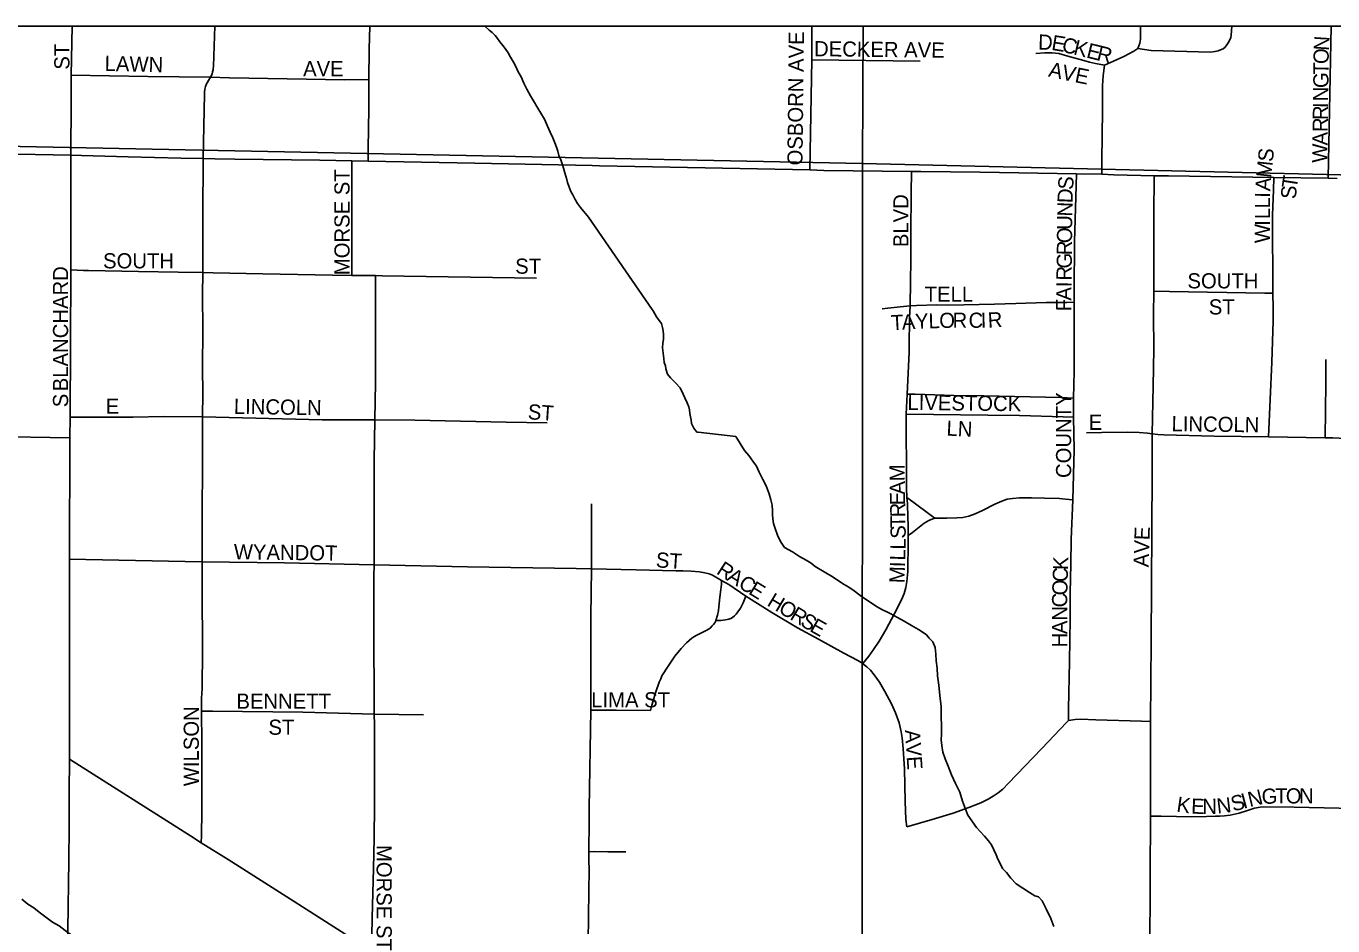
# Model space of a CAD drawing. Extents: x 0 to 68, y 0 to 52.9.
# Drawn here: x 43.794 to 44.871, y 41.267 to 42.008 of the extents above; entities that cross this region are included whole.
import ezdxf

# ---------------------------------------------------------------- set-up
doc = ezdxf.new("R2010")
doc.units = 0
for name, color, linetype in [('Default', 7, 'Continuous'), ('GM_X_Minor_River', 7, 'Continuous'), ('GM_X_State_Route', 7, 'Continuous')]:
    doc.layers.add(name, color=color, linetype=linetype)

msp = doc.modelspace()

# ---------------------------------------------------------------- linework, layer by layer
at = {"layer": 'Default'}
msp.add_line((41.1051, 42.0083), (50.3451, 42.0083), dxfattribs=at)
for points in [[(43.8309, 41.9678), (43.8317, 42.0083)], [(43.9457, 41.9661), (43.947, 41.9688), (43.9475, 41.9706), (43.9479, 41.9723), (43.948, 41.9731), (43.9483, 41.9752), (43.9492, 42.0083)], [(44.0763, 41.9642), (44.0767, 41.9894), (44.077, 42.0083)], [(44.4416, 41.9806), (44.4416, 41.9888), (44.4416, 42.0083)], [(45.8294, 42.0083), (45.8284, 41.8633), (44.4833, 41.8951), (44.484, 42.0083)], [(44.7106, 41.9899), (44.7121, 41.9942), (44.7127, 41.9977), (44.7128, 42.0016), (44.7128, 42.0083)], [(44.7106, 41.9899), (44.7215, 41.9882), (44.7704, 41.9869), (44.774, 41.9873), (44.7766, 41.9879), (44.7787, 41.9887), (44.7808, 41.9897), (44.7825, 41.9911), (44.7839, 41.9929), (44.785, 41.9945), (44.7863, 41.9969), (44.7871, 41.999), (44.7874, 42.0009), (44.7879, 42.0083)], [(44.8675, 41.8829), (44.87, 42.0083)], [(44.6264, 41.9857), (44.6339, 41.9862), (44.6398, 41.9863), (44.6452, 41.9857), (44.6528, 41.9836), (44.6589, 41.982), (44.6639, 41.9804), (44.6705, 41.9786), (44.6757, 41.9774), (44.683, 41.9761)], [(44.683, 41.9761), (44.6905, 41.9795), (44.699, 41.9833), (44.7071, 41.9877), (44.7106, 41.9899)], [(44.44, 41.8898), (44.4416, 41.9806)], [(44.4416, 41.9806), (44.531, 41.9795)], [(44.6808, 41.8863), (44.6809, 41.8976), (44.6812, 41.9387), (44.6814, 41.9592), (44.6815, 41.9634), (44.682, 41.9672), (44.6825, 41.9716), (44.683, 41.9761)], [(43.8305, 41.9018), (43.8307, 41.9461), (43.8309, 41.9678)], [(43.8309, 41.9678), (43.894, 41.9668), (43.9457, 41.9661)], [(43.9396, 41.8991), (43.9407, 41.9526), (43.9407, 41.9539), (43.9411, 41.9564), (43.9417, 41.9585), (43.9425, 41.9608), (43.943, 41.9617), (43.944, 41.9635), (43.9457, 41.9661)], [(43.9457, 41.9661), (43.9614, 41.9658), (44.0564, 41.964), (44.0763, 41.9642)], [(44.0757, 41.8969), (44.0758, 41.9073), (44.0764, 41.9402), (44.0763, 41.9642)], [(43.8304, 41.8074), (43.8305, 41.9018)], [(43.9393, 41.8051), (43.9393, 41.8523), (43.9396, 41.8991)], [(44.0622, 41.8027), (44.0623, 41.8124), (44.0624, 41.8368), (44.0623, 41.8524), (44.0623, 41.881), (44.0623, 41.8928), (44.0623, 41.8972)], [(44.5226, 41.7778), (44.5226, 41.7804), (44.523, 41.7951), (44.5233, 41.8181), (44.5233, 41.846), (44.5236, 41.8624), (44.5235, 41.8707), (44.5238, 41.8885)], [(44.658, 41.7807), (44.658, 41.7898), (44.6583, 41.8307), (44.6593, 41.8673), (44.6599, 41.8866)], [(44.7237, 41.8198), (44.7237, 41.8594), (44.7239, 41.8781), (44.724, 41.885)], [(44.8219, 41.7881), (44.8216, 41.8526), (44.8223, 41.873), (44.8226, 41.8835)], [(44.7238, 41.7898), (44.7237, 41.8034), (44.7237, 41.8198)], [(43.83, 41.686), (43.8302, 41.7461), (43.8304, 41.8074)], [(43.8304, 41.8074), (43.8411, 41.8069), (43.8452, 41.8068), (43.8862, 41.8059), (43.9191, 41.8056), (43.9393, 41.8051)], [(43.9392, 41.6863), (43.9393, 41.7058), (43.9391, 41.7263), (43.9394, 41.7581), (43.9392, 41.7868), (43.9393, 41.8051)], [(43.9393, 41.8051), (43.9478, 41.8049), (43.9889, 41.8041), (44.0463, 41.8029), (44.0622, 41.8027)], [(44.0622, 41.8027), (44.0819, 41.8026)], [(44.0813, 41.6837), (44.0819, 41.7142), (44.0819, 41.7931), (44.0819, 41.8026)], [(44.0819, 41.8026), (44.0874, 41.8025), (44.2145, 41.8004)], [(44.5226, 41.7778), (44.528, 41.7781), (44.5448, 41.7785), (44.5543, 41.7784), (44.5922, 41.7792), (44.61, 41.7797), (44.6348, 41.7804), (44.6519, 41.7806), (44.658, 41.7807)], [(44.6574, 41.7015), (44.658, 41.7235), (44.6581, 41.7604), (44.658, 41.7807)], [(44.7224, 41.6722), (44.723, 41.7114), (44.7236, 41.7421), (44.7234, 41.7707), (44.7238, 41.7898)], [(44.7238, 41.7898), (44.7366, 41.7896), (44.8153, 41.7882), (44.8219, 41.7881)], [(44.8183, 41.6698), (44.8211, 41.7314), (44.822, 41.7653), (44.822, 41.7757), (44.8219, 41.7881)], [(44.4995, 41.7752), (44.5043, 41.7757), (44.5145, 41.7768), (44.5226, 41.7778)], [(44.5203, 41.705), (44.5218, 41.7396), (44.522, 41.7494), (44.5222, 41.7625), (44.5223, 41.7681), (44.5226, 41.7778)], [(44.865, 41.6689), (44.8656, 41.7139), (44.8656, 41.7334)], [(44.5195, 41.6885), (44.5203, 41.705)], [(44.5203, 41.705), (44.5269, 41.7048), (44.5588, 41.7038), (44.5834, 41.7036), (44.6471, 41.7022), (44.6574, 41.7015)], [(44.6574, 41.686), (44.6574, 41.7015)], [(43.8297, 41.669), (43.83, 41.686)], [(43.83, 41.686), (43.8412, 41.686), (43.8819, 41.686), (43.907, 41.6866), (43.9392, 41.6863)], [(43.9389, 41.5666), (43.9392, 41.6863)], [(43.9392, 41.6863), (44.0379, 41.6838), (44.0813, 41.6837)], [(44.0806, 41.5643), (44.0806, 41.6502), (44.0813, 41.6837)], [(44.0813, 41.6837), (44.1142, 41.6836), (44.1896, 41.6817), (44.2233, 41.6812)], [(44.5195, 41.6885), (44.5869, 41.6876), (44.613, 41.6872), (44.649, 41.6863), (44.6574, 41.686)], [(44.5201, 41.6197), (44.5197, 41.6278), (44.5196, 41.6302), (44.5195, 41.6885)], [(44.6569, 41.6177), (44.6579, 41.6594), (44.6574, 41.686)], [(44.6682, 41.6729), (44.6807, 41.6734), (44.7021, 41.6735), (44.7117, 41.6733), (44.7184, 41.6727), (44.7224, 41.6722)], [(44.721, 41.4351), (44.7215, 41.5009), (44.7223, 41.6399), (44.7224, 41.6722)], [(44.7224, 41.6722), (44.7269, 41.6716), (44.7318, 41.6713), (44.7733, 41.6704), (44.8183, 41.6698)], [(44.8183, 41.6698), (44.865, 41.6689)], [(44.865, 41.6689), (44.8713, 41.6688), (44.8766, 41.6687), (44.8817, 41.6684), (44.8859, 41.6678), (44.8924, 41.6668), (44.9117, 41.6631), (44.9159, 41.6624), (44.9205, 41.6618), (44.9244, 41.6613), (44.9279, 41.6612), (44.9401, 41.6611), (44.95, 41.661)], [(44.5212, 41.5884), (44.5212, 41.5958), (44.5205, 41.6131), (44.5204, 41.6147), (44.5201, 41.6197)], [(44.5201, 41.6197), (44.525, 41.6161), (44.5401, 41.6048), (44.5431, 41.6026)], [(44.5431, 41.6026), (44.5529, 41.6028), (44.5613, 41.6029), (44.5662, 41.6033), (44.571, 41.6043), (44.5764, 41.6062), (44.5823, 41.6091), (44.5925, 41.6142), (44.5983, 41.6168), (44.6028, 41.6183), (44.6071, 41.6189), (44.613, 41.6194), (44.6229, 41.6194), (44.6336, 41.6192), (44.6459, 41.6188), (44.6508, 41.6183), (44.6569, 41.6177)], [(44.2598, 41.5609), (44.2598, 41.6144)], [(44.6533, 41.4358), (44.6532, 41.4454), (44.6542, 41.4844), (44.6546, 41.5196), (44.6548, 41.541), (44.6553, 41.5648), (44.6555, 41.5853), (44.6569, 41.6177)], [(44.5212, 41.5884), (44.5246, 41.591), (44.5344, 41.5986), (44.5381, 41.6008), (44.5401, 41.6016), (44.5431, 41.6026)], [(44.4837, 41.4828), (44.4885, 41.489), (44.4926, 41.4943), (44.4971, 41.5012), (44.5026, 41.5105), (44.5099, 41.5242), (44.5156, 41.5353), (44.5178, 41.5407), (44.5192, 41.5455), (44.52, 41.5505), (44.5207, 41.5588), (44.5212, 41.5834), (44.5212, 41.5884)], [(43.8295, 41.5688), (43.8428, 41.5686), (43.9247, 41.5671), (43.9389, 41.5666)], [(43.9384, 41.4437), (43.9384, 41.4542), (43.9388, 41.462), (43.9391, 41.4942), (43.9388, 41.5434), (43.9389, 41.5666)], [(43.9389, 41.5666), (44.0067, 41.5658), (44.0806, 41.5643)], [(44.0807, 41.4412), (44.0808, 41.4519), (44.0803, 41.507), (44.0805, 41.5548), (44.0806, 41.5643)], [(44.0806, 41.5643), (44.1576, 41.5626), (44.2474, 41.5612), (44.2598, 41.5609)], [(44.2593, 41.4444), (44.2595, 41.5216), (44.2598, 41.5609)], [(44.2598, 41.5609), (44.2967, 41.56), (44.3294, 41.5593), (44.3353, 41.5592), (44.3421, 41.559), (44.3491, 41.5584), (44.3533, 41.5577), (44.3569, 41.5569), (44.3597, 41.5558)], [(44.3672, 41.5514), (44.3597, 41.5558)], [(44.3625, 41.5183), (44.3638, 41.5226), (44.3646, 41.5267), (44.3655, 41.5351), (44.3662, 41.5419), (44.367, 41.5479), (44.3672, 41.5514)], [(44.3873, 41.5385), (44.3731, 41.5479), (44.3672, 41.5514)], [(44.3625, 41.5183), (44.3666, 41.5184), (44.3704, 41.5189), (44.3732, 41.5195), (44.3748, 41.5201), (44.3761, 41.5209), (44.3778, 41.5222), (44.3792, 41.5235), (44.3807, 41.5254), (44.3827, 41.5285), (44.385, 41.533), (44.3873, 41.5385)], [(44.4837, 41.4828), (44.4796, 41.4854), (44.4679, 41.4914), (44.447, 41.5028), (44.4297, 41.5122), (44.4086, 41.5248), (44.3873, 41.5385)], [(44.3086, 41.4442), (44.3096, 41.4484), (44.313, 41.4595), (44.3158, 41.4675), (44.317, 41.4702), (44.318, 41.4727), (44.3231, 41.4808), (44.3286, 41.4889), (44.3338, 41.4953), (44.3383, 41.5), (44.3427, 41.5037), (44.3444, 41.5048), (44.3469, 41.5062), (44.355, 41.5103), (44.3577, 41.5121), (44.3595, 41.5138), (44.3605, 41.5151), (44.3615, 41.5164), (44.3624, 41.5181), (44.3625, 41.5183)], [(44.5199, 41.3481), (44.5192, 41.3543), (44.5187, 41.369), (44.518, 41.3961), (44.517, 41.4125), (44.5162, 41.4217), (44.5154, 41.4266), (44.5136, 41.4339), (44.5106, 41.4421), (44.5074, 41.4496), (44.5019, 41.4597), (44.4973, 41.4675), (44.4931, 41.4736), (44.4899, 41.4774), (44.487, 41.4802), (44.4838, 41.4827), (44.4837, 41.4828)], [(43.9381, 41.335), (43.9382, 41.341), (43.9386, 41.3611), (43.9385, 41.3929), (43.9386, 41.4173), (43.9384, 41.4437)], [(43.9384, 41.4437), (43.9474, 41.4436), (44.0218, 41.4428), (44.0807, 41.4412)], [(44.076, 41.2479), (44.0773, 41.2513), (44.0787, 41.256), (44.0788, 41.2582), (44.0791, 41.2732), (44.0801, 41.314), (44.0806, 41.3389), (44.0809, 41.366), (44.081, 41.4325), (44.0807, 41.4412)], [(44.0807, 41.4412), (44.1213, 41.4405)], [(44.2577, 41.3276), (44.258, 41.3529), (44.2581, 41.3635), (44.2593, 41.4444)], [(44.2593, 41.4444), (44.2676, 41.4444), (44.2803, 41.4444), (44.3086, 41.4442)], [(44.5199, 41.3481), (44.5408, 41.3542), (44.5581, 41.3595), (44.5712, 41.3641), (44.5811, 41.3681), (44.5871, 41.3709), (44.5913, 41.3734), (44.5954, 41.3762), (44.5991, 41.3794), (44.6037, 41.3841), (44.6242, 41.4054), (44.6312, 41.4129), (44.6517, 41.4343), (44.6533, 41.4358)], [(44.6533, 41.4358), (44.6587, 41.4367), (44.6636, 41.4371), (44.6759, 41.4365), (44.7134, 41.4353), (44.721, 41.4351)], [(44.7209, 41.357), (44.7208, 41.4151), (44.721, 41.4351)], [(43.8266, 41.066), (43.8267, 41.0706), (43.8269, 41.1158), (43.8274, 41.1526), (43.8276, 41.2059), (43.8281, 41.2634), (43.8288, 41.3205), (43.8292, 41.3479), (43.8291, 41.3767), (43.8294, 41.404)], [(44.7209, 41.357), (44.7297, 41.357), (44.7551, 41.3566), (44.7671, 41.3568), (44.7746, 41.3569), (44.7781, 41.3569), (44.7819, 41.3572), (44.7865, 41.3579), (44.7941, 41.3595), (44.8008, 41.3617), (44.8067, 41.3635), (44.8113, 41.3644), (44.8145, 41.3647), (44.8394, 41.3644), (44.9134, 41.3628)], [(44.7198, 41.1799), (44.7201, 41.2312), (44.7206, 41.2883), (44.7206, 41.3087), (44.7209, 41.357)], [(44.2577, 41.3276), (44.2628, 41.3278), (44.2733, 41.3275), (44.2881, 41.3275)], [(44.257, 41.1348), (44.257, 41.1441), (44.2571, 41.1474), (44.257, 41.1797), (44.257, 41.1919), (44.2573, 41.2525), (44.2574, 41.2751), (44.2579, 41.3137), (44.2577, 41.3199), (44.2577, 41.3276)]]:
    msp.add_lwpolyline(points, dxfattribs=at)
for points in [[(43.2028, 41.9209), (44.4833, 41.8951), (44.4829, 40.5718), (43.1833, 40.5874), (43.183, 40.6024)], [(44.4833, 41.8951), (45.8284, 41.8633), (45.8139, 40.5412), (44.4829, 40.5718)]]:
    msp.add_lwpolyline(points, close=True, dxfattribs=at)
at = {"layer": 'GM_X_Minor_River'}
for points in [[(44.1719, 42.0083), (44.172, 42.0082), (44.1755, 42.0051), (44.1779, 42.0031), (44.1804, 42.0005), (44.1824, 41.998), (44.1843, 41.9954), (44.1868, 41.9924), (44.1887, 41.9898), (44.1911, 41.9863), (44.1931, 41.9827), (44.1955, 41.9787), (44.1974, 41.9751), (44.1994, 41.9706), (44.2018, 41.9665), (44.2042, 41.9614), (44.2066, 41.9564), (44.2095, 41.9508), (44.2182, 41.9366), (44.2211, 41.9315), (44.2235, 41.9259), (44.2259, 41.9209), (44.2279, 41.9163), (44.2302, 41.9108), (44.2312, 41.9077), (44.2321, 41.9052), (44.2331, 41.9017), (44.2345, 41.8981), (44.2359, 41.8941), (44.2369, 41.8911), (44.2378, 41.8875), (44.2387, 41.8845), (44.2397, 41.882), (44.2401, 41.8795)], [(44.2401, 41.8795), (44.2411, 41.8764), (44.243, 41.8719), (44.2445, 41.8693), (44.2464, 41.8653), (44.2483, 41.8622), (44.2508, 41.8587), (44.2574, 41.8509)], [(44.2574, 41.8509), (44.3099, 41.7746)], [(44.3099, 41.7746), (44.3107, 41.7737), (44.3136, 41.7687), (44.3156, 41.7656), (44.3176, 41.7631), (44.3185, 41.76), (44.3189, 41.757), (44.3194, 41.754), (44.3193, 41.75), (44.3187, 41.747), (44.3186, 41.743), (44.3195, 41.7344), (44.3199, 41.7309), (44.3209, 41.7284), (44.3213, 41.7259), (44.3227, 41.7213), (44.3252, 41.7183), (44.3291, 41.7142), (44.333, 41.7101), (44.3354, 41.705), (44.3369, 41.702), (44.3388, 41.6979), (44.3402, 41.6944), (44.3407, 41.6919), (44.3411, 41.6889), (44.3416, 41.6863), (44.342, 41.6838), (44.3425, 41.6808), (44.3444, 41.6768), (44.3468, 41.6737), (44.3478, 41.6737), (44.3789, 41.67)], [(44.3789, 41.67), (44.3862, 41.6584), (44.3896, 41.6543), (44.393, 41.6497), (44.3959, 41.6456), (44.3983, 41.6406), (44.4012, 41.6345), (44.4041, 41.6294), (44.4065, 41.6228), (44.4079, 41.6178), (44.4088, 41.6133), (44.4092, 41.6087), (44.4092, 41.6057), (44.4096, 41.6022), (44.41, 41.5982), (44.4114, 41.5942), (44.4133, 41.5886), (44.4157, 41.5835), (44.4192, 41.5785), (44.4256, 41.5748), (44.4315, 41.5712), (44.437, 41.5681), (44.441, 41.5655), (44.4444, 41.5629), (44.4593, 41.5541), (44.4637, 41.551), (44.4682, 41.5479), (44.4722, 41.5458), (44.4766, 41.5427), (44.4811, 41.5391), (44.486, 41.536), (44.4905, 41.5329), (44.4949, 41.5298), (44.4999, 41.5272), (44.5039, 41.5251), (44.5063, 41.524), (44.5123, 41.5209), (44.5178, 41.5178), (44.5237, 41.5142), (44.5297, 41.511), (44.5326, 41.509), (44.5361, 41.5064), (44.5385, 41.5038), (44.5415, 41.5008), (44.5434, 41.4962), (44.5438, 41.4907), (44.5442, 41.4852), (44.5451, 41.4791), (44.5454, 41.4726), (44.5463, 41.4651), (44.5471, 41.4565), (44.5484, 41.4475), (44.5483, 41.4389), (44.5486, 41.4314), (44.5485, 41.4244), (44.5484, 41.4199), (44.5488, 41.4154), (44.5497, 41.4098), (44.5516, 41.4043), (44.554, 41.3982), (44.5568, 41.3911), (44.5602, 41.384), (44.5636, 41.3769), (44.5659, 41.3694), (44.5683, 41.3628), (44.5702, 41.3578), (44.5775, 41.3476), (44.5805, 41.3445), (44.5839, 41.3404), (44.5873, 41.3368), (44.5898, 41.3333), (44.5917, 41.3292), (44.5936, 41.3252), (44.595, 41.3216), (44.597, 41.3181), (44.5989, 41.314), (44.6023, 41.3105), (44.6058, 41.3059), (44.6102, 41.3013), (44.6156, 41.2977), (44.6211, 41.294), (44.6255, 41.2914), (44.6285, 41.2904), (44.6315, 41.2873), (44.6348, 41.2807), (44.6387, 41.2726), (44.6411, 41.2661)], [(43.7902, 41.2887), (43.7951, 41.2846), (43.8001, 41.2815), (43.8045, 41.2779), (43.81, 41.2738), (43.8154, 41.2696), (43.8209, 41.2665), (43.8258, 41.2629), (43.8312, 41.2588), (43.8397, 41.2531), (43.8451, 41.249), (43.8505, 41.2444), (43.857, 41.2402), (43.8624, 41.2366)]]:
    msp.add_lwpolyline(points, dxfattribs=at)
at = {"layer": 'GM_X_State_Route'}
for points in [[(43.4443, 41.9196), (43.4737, 41.9188), (43.5039, 41.9179), (43.557, 41.9163), (43.6121, 41.9134), (43.6264, 41.9127), (43.6794, 41.9092), (43.716, 41.9062), (43.7405, 41.9041), (43.7569, 41.9034), (43.8305, 41.9018), (43.8394, 41.9016), (43.8779, 41.9006)], [(43.8779, 41.9006), (43.9213, 41.8995), (43.9396, 41.8991), (43.9492, 41.899), (43.9657, 41.8986), (44.0358, 41.8977), (44.0623, 41.8972)], [(44.0623, 41.8972), (44.0757, 41.8969), (44.1636, 41.8953), (44.2605, 41.8933)], [(44.2605, 41.8933), (44.2666, 41.8932), (44.3248, 41.8921), (44.44, 41.8898), (44.4514, 41.8894), (44.5238, 41.8885), (44.5315, 41.8884), (44.5805, 41.888), (44.6599, 41.8866), (44.6808, 41.8863), (44.6907, 41.8857), (44.724, 41.885), (44.7357, 41.8848), (44.8226, 41.8835), (44.8675, 41.8829), (44.8748, 41.8828)], [(43.2041, 41.6826), (43.2294, 41.6823), (43.2908, 41.681), (43.3247, 41.6802), (43.4055, 41.6782), (43.4405, 41.6772), (43.4626, 41.6761), (43.61, 41.6726), (43.655, 41.6715), (43.7001, 41.6712), (43.8297, 41.669)], [(43.8297, 41.669), (43.8295, 41.5688), (43.8294, 41.4067)], [(43.8294, 41.4067), (43.8294, 41.404), (43.9291, 41.3407), (43.9381, 41.335), (43.9604, 41.3212), (44.0117, 41.2885), (44.0634, 41.2557)]]:
    msp.add_lwpolyline(points, dxfattribs=at)

# ---------------------------------------------------------------- texts
at = {"layer": 'Default'}
for s, rotation, p in [('OSBORN AVE', 89.3493, (44.4339, 41.8934)), ('DECKER AVE', 359.3493, (44.4434, 41.9835)), ('D', 358.4477, (44.6281, 41.989)), ('E', 350.641, (44.6387, 41.9888)), ('C', 346.5175, (44.6471, 41.9874)), ('K', 346.25, (44.6567, 41.9851)), ('N', 86.3037, (44.8679, 41.9878)), ('ST', 90, (43.8294, 41.9724)), ('E', 346.2711, (44.6674, 41.9825)), ('R', 346.2464, (44.6759, 41.9804)), ('O', 89.2495, (44.8678, 41.977)), ('LAWN', 358.6368, (43.8583, 41.9714)), ('AVE', 0, (44.0221, 41.967)), ('A', 347.7297, (44.6362, 41.9669)), ('V', 347.8119, (44.6469, 41.9645)), ('T', 89.2545, (44.8677, 41.9682)), ('E', 348.591, (44.6579, 41.9622)), ('G', 89.2495, (44.8676, 41.9572)), ('N', 89.227, (44.8674, 41.9462)), ('R', 89.2471, (44.8672, 41.9308)), ('I', 89.2233, (44.8673, 41.9407)), ('R', 89.2576, (44.8671, 41.9209)), ('A', 89.2349, (44.8669, 41.9099)), ('W', 89.2603, (44.8667, 41.8956)), ('S', 84.0882, (44.8218, 41.896)), ('MORSE ST', 90, (44.0604, 41.803)), ('M', 84.1245, (44.8204, 41.8829)), ('S', 86.0351, (44.657, 41.8731)), ('A', 85.5594, (44.8196, 41.872)), ('T', 81.2788, (44.8414, 41.8739)), ('BLVD', 90, (44.5213, 41.8261)), ('D', 87.7041, (44.6566, 41.8622)), ('I', 88.7755, (44.8195, 41.8667)), ('L', 89.9572, (44.8195, 41.858)), ('S', 86.6095, (44.8409, 41.8655)), ('N', 89.317, (44.6565, 41.8513)), ('L', 89.9453, (44.8195, 41.8492)), ('U', 89.317, (44.6563, 41.8403)), ('W', 89.9496, (44.8194, 41.8294)), ('I', 89.9573, (44.8195, 41.8437)), ('O', 89.317, (44.6562, 41.8293)), ('R', 89.32, (44.6561, 41.8194)), ('SOUTH', 0, (43.8571, 41.8086)), ('ST', 0, (44.197, 41.8042)), ('G', 89.317, (44.656, 41.8084)), ('BLANCHARD', 90, (43.8283, 41.7073)), ('R', 89.32, (44.6558, 41.7985)), ('SOUTH', 0, (44.7514, 41.7921)), ('TELL', 0, (44.5347, 41.7811)), ('A', 89.317, (44.6556, 41.782)), ('I', 89.315, (44.6558, 41.793)), ('F', 89.317, (44.6555, 41.7732)), ('ST', 0, (44.769, 41.7706)), ('T', 3.2526, (44.5073, 41.7575)), ('A', 3.215, (44.5161, 41.758)), ('Y', 2.8209, (44.5271, 41.7586)), ('L', 1.7763, (44.538, 41.7591)), ('O', 1.0929, (44.5468, 41.7594)), ('R', 0.1214, (44.5577, 41.7596)), ('C', 0.1128, (44.5709, 41.7596)), ('I', 0.9397, (44.581, 41.7596)), ('R', 2.8197, (44.587, 41.7597)), ('COUNTY', 90, (44.6555, 41.6358)), ('S', 90, (43.8283, 41.6941)), ('E', 0, (43.8593, 41.6887)), ('LINCOLN', 359.0613, (43.9649, 41.6887)), ('ST', 356.1879, (44.2071, 41.6843)), ('LIVESTOCK', 359.2563, (44.5204, 41.692)), ('E', 0, (44.67, 41.6755)), ('LINCOLN', 359.1935, (44.7382, 41.6744)), ('LN', 356.989, (44.5524, 41.6708)), ('M', 90.972, (44.5183, 41.6332)), ('A', 90.9399, (44.5185, 41.6222)), ('E', 90.9562, (44.5186, 41.6134)), ('R', 90.9795, (44.5188, 41.6035)), ('T', 90.9497, (44.5189, 41.5947)), ('S', 90.6733, (44.5191, 41.5858)), ('AVE', 88.0264, (44.7193, 41.5621)), ('WYANDOT', 359.2047, (43.9649, 41.5688)), ('L', 88.1691, (44.5186, 41.5676)), ('L', 89.1412, (44.5189, 41.5767)), ('ST', 356.1879, (44.3127, 41.5622)), ('R', 326.97, (44.3622, 41.5574)), ('I', 88.1863, (44.5185, 41.5621)), ('K', 87.9452, (44.6529, 41.5597)), ('A', 328.1913, (44.3708, 41.5519)), ('C', 328.3944, (44.3802, 41.546)), ('M', 88.1782, (44.518, 41.5489)), ('C', 87.984, (44.6526, 41.5498)), ('E', 328.3974, (44.3886, 41.5408)), ('O', 88.5357, (44.6523, 41.5389)), ('H', 329.1, (44.4039, 41.5311)), ('O', 329.099, (44.4133, 41.5254)), ('C', 89.83, (44.6522, 41.5291)), ('R', 329.1156, (44.4228, 41.5198)), ('S', 329.0925, (44.4313, 41.5147)), ('N', 89.9781, (44.6522, 41.5181)), ('E', 330.3908, (44.4391, 41.51)), ('A', 89.9928, (44.6522, 41.5071)), ('H', 89.9781, (44.6522, 41.4961)), ('BENNETT', 0, (43.9671, 41.4456)), ('LIMA ST', 0, (44.2597, 41.4467)), ('WILSON', 90, (43.9361, 41.3817)), ('ST', 0, (43.9935, 41.4241)), ('A', 273.9159, (44.5183, 41.428)), ('V', 273.9159, (44.5191, 41.4171)), ('E', 273.8832, (44.5198, 41.4061)), ('K', 351.7308, (44.7419, 41.3609)), ('E', 357.4412, (44.7542, 41.3592)), ('N', 0.6462, (44.7637, 41.3588)), ('N', 6.7439, (44.7762, 41.359)), ('S', 15.3447, (44.7891, 41.3607)), ('I', 15.2666, (44.7976, 41.363)), ('N', 13.5221, (44.8028, 41.3644)), ('G', 3.1932, (44.8129, 41.3669)), ('T', 0.082, (44.8237, 41.3675)), ('O', 0, (44.8325, 41.3675)), ('N', 0, (44.8435, 41.3675)), ('MORSE ST', 270, (44.0827, 41.3333))]:
    msp.add_text(s, height=0.0125, rotation=rotation, dxfattribs=at).set_placement(p)

doc.saveas('drawing.dxf')
